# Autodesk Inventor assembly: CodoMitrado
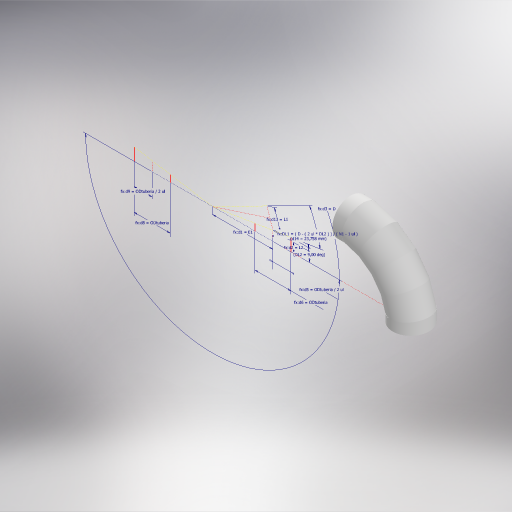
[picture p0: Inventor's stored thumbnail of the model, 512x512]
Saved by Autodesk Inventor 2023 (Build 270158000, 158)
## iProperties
RuleStatus: InUse
Created: 2023-01
Part Number: CodoMitrado
Document SubType Name: Assembly
Designer: Nelson C Agudelo A
L2: 60,344 mm
L1: 120,689 mm
Espesor: 2,500 mm
ODtuberia: 273,000 mm
N1: 5,000 ul
E1: 381,000 mm
D: 90,00 deg
Recorte: 21,619 mm
Author: Nelson C Agudelo A
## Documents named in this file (4)
- C:\Users\Camilo\OneDrive\Documents\09-Proyectos Inventor 2023\02-CodoMitrado\CodoMitrado.iam
- C:\Users\Camilo\OneDrive\Documents\09-Proyectos Inventor 2023\02-CodoMitrado\02-L2.ipt
- C:\Users\Camilo\OneDrive\Documents\09-Proyectos Inventor 2023\02-CodoMitrado\03-L1.ipt
- C:\Users\Camilo\OneDrive\Documents\09-Proyectos Inventor 2023\02-CodoMitrado\01-Esquema Codo Mitrado.ipt
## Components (7 placed, 3 different names)
1. 02-L2:1 — Mate:3, Flush:2, Flush:3, Mate:4, Flush:5, Mate:6
2. 02-L2:2 — Mate:4, Flush:4, Mate:6
3. 01-Esquema Codo Mitrado:1 — Mate:7
4. 03-L1:1 — Mate:3, Flush:2, Flush:3
5. 03-L1:2
6. 03-L1:3
7. 03-L1:4
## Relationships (8: Mate 4, Flush 4)
- Mate:3: 02-L2:1 ↔ 03-L1:1
- Flush:2: 02-L2:1 ↔ 03-L1:1
- Flush:3: 02-L2:1 ↔ 03-L1:1
- Mate:4: 02-L2:1 ↔ 02-L2:2
- Flush:4: 02-L2:2
- Flush:5: 02-L2:1
- Mate:6: 02-L2:1 ↔ 02-L2:2
- Mate:7: 01-Esquema Codo Mitrado:1
